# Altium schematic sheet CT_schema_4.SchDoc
size 299 x 185 mm
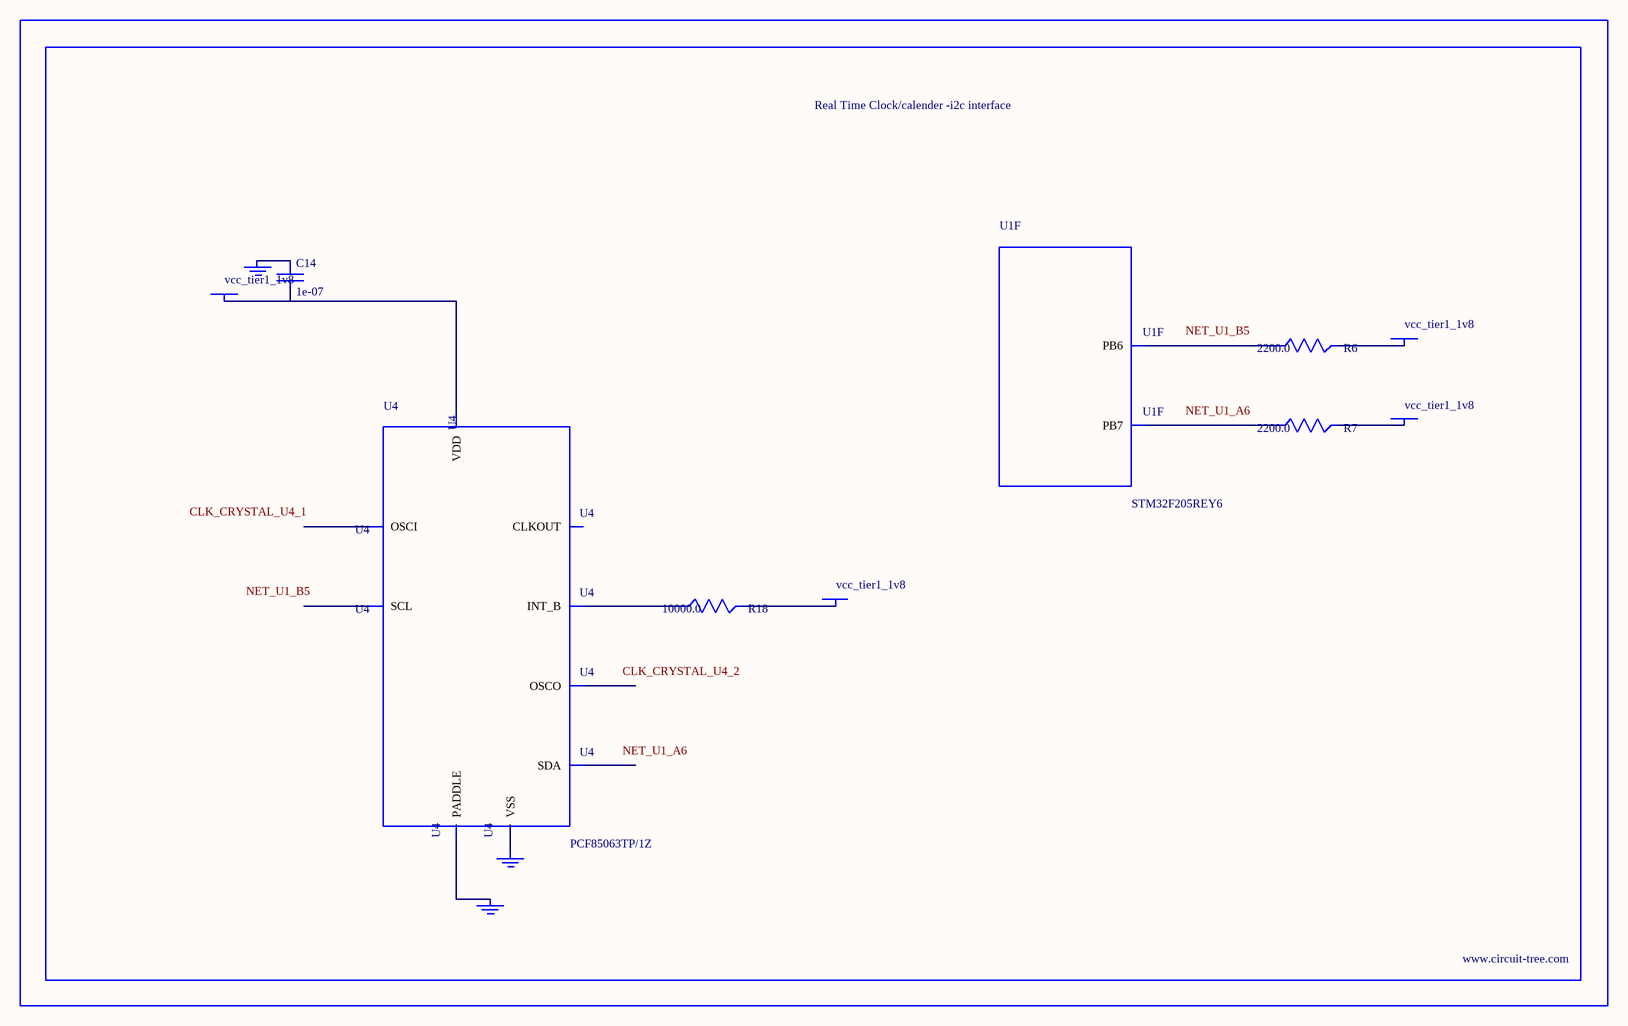
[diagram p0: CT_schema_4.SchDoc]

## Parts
BORDER3  (no value)
C14  1e-07  [C0402]
GND_INSTANCE_3_0  (no value)
GND_INSTANCE_3_1  (no value)
GND_INSTANCE_3_2  (no value)
POWER_INSTANCE_3_0  vcc_tier1_1v8
POWER_INSTANCE_3_1  vcc_tier1_1v8
POWER_INSTANCE_3_2  vcc_tier1_1v8
POWER_INSTANCE_3_3  vcc_tier1_1v8
R6  2200.0  [R0603]
R7  2200.0  [R0603]
R18  10000.0  [R0603]
U1  STM32F205REY6  [WLCSP66]  (part F of 7)
U4  PCF85063TP/1Z  [SON-8]

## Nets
NetC14_1: C14.1 GND_INSTANCE_3_0.0(GND)
NetC14_2: C14.2 POWER_INSTANCE_3_1.0(PWR) U4.8(VDD)
NetGND_INSTANCE_3_1_0: GND_INSTANCE_3_1.0(GND) U4.PAD(PADDLE)
NetGND_INSTANCE_3_2_0: GND_INSTANCE_3_2.0(GND) U4.4(VSS)
NetPOWER_INSTANCE_3_0_0: POWER_INSTANCE_3_0.0(PWR) R18.2
NetPOWER_INSTANCE_3_2_0: POWER_INSTANCE_3_2.0(PWR) R6.2
NetPOWER_INSTANCE_3_3_0: POWER_INSTANCE_3_3.0(PWR) R7.2
NetR6_1: R6.1 U1.B5(PB6)
NetR7_1: R7.1 U1.A6(PB7)
NetR18_1: R18.1 U4.3(INT_B)

Not connected (* = marked no-connect by the designer): U4 1(OSCI) 2(OSCO) 5(SDA) 6(SCL) 7(CLKOUT)

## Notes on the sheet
- Labels drawn without touching a wire or pin: CLK_CRYSTAL_U4_1, CLK_CRYSTAL_U4_2, NET_U1_A6, NET_U1_B5

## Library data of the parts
BORDER3 = BORDER_PAGE3
C14 = C0402C104K3RACTU
GND_INSTANCE_3_0-GND_INSTANCE_3_2 = GND
POWER_INSTANCE_3_0-POWER_INSTANCE_3_3 = PWR
R6 R7 = RC0603JR-072K2L
R18 = RC0603JR-0710KL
